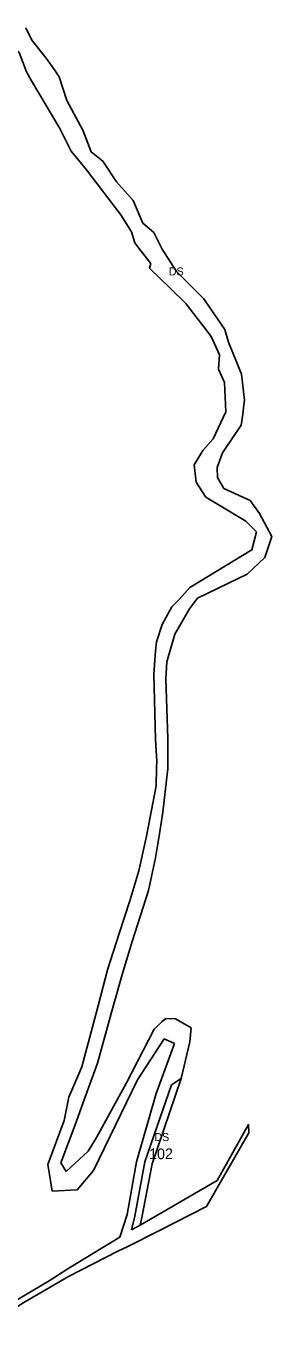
# Model space of a CAD drawing. Extents: x -477304 to -465641, y -1159113 to -1149285.
# Drawn here: x -468631 to -468355, y -1158263 to -1156790 of the extents above; entities that cross this region are included whole.
import ezdxf

# ---------------------------------------------------------------- set-up
doc = ezdxf.new("R2010")
doc.units = 0
for name, color, linetype in [('14', 7, 'Continuous'), ('35', 7, 'Continuous'), ('60', 7, 'Continuous')]:
    doc.layers.add(name, color=color, linetype=linetype)

msp = doc.modelspace()

# ---------------------------------------------------------------- linework, layer by layer
at = {"layer": '14'}
for p, q in [((-468456.8, -1157973.4), (-468467.9, -1157980.6)), ((-468467.9, -1157980.6), (-468497.7, -1158067.2)), ((-468497.7, -1158067.2), (-468509.1, -1158128.1)), ((-468509.1, -1158128.1), (-468512.6, -1158143.7)), ((-468512.6, -1158143.7), (-468503, -1158138.1)), ((-468503, -1158138.1), (-468501.1, -1158129.7))]:
    msp.add_line(p, q, dxfattribs=at)
msp.add_lwpolyline([(-468501.1, -1158129.7), (-468489.7, -1158069.3), (-468456.8, -1157973.4)], dxfattribs=at)
at = {"layer": '35'}
for p, q in [((-468630.9, -1156841.5), (-468625.1, -1156851.4)), ((-468594.2, -1156847.1), (-468599.5, -1156839.4)), ((-468625.1, -1156851.4), (-468593.4, -1156905.3)), ((-468558.2, -1156931.4), (-468567.6, -1156907)), ((-468563.5, -1156951.5), (-468551.2, -1156967.3)), ((-468551.2, -1156967.3), (-468539.3, -1156983.1)), ((-468510.8, -1156986.2), (-468529.8, -1156965.2)), ((-468500.2, -1157011.6), (-468510.8, -1156986.2)), ((-468512.9, -1157021.4), (-468509.2, -1157033.6)), ((-468509.2, -1157033.6), (-468504.6, -1157039.7)), ((-468478.4, -1157040.7), (-468480.9, -1157035.7)), ((-468504.6, -1157039.7), (-468491.1, -1157057.1)), ((-468468.9, -1157085.1), (-468451.6, -1157102.1)), ((-468431.5, -1157128.2), (-468423.1, -1157139.1)), ((-468387.7, -1157226.2), (-468386.3, -1157215.7)), ((-468408.8, -1157310.1), (-468416.2, -1157297.5)), ((-468440.2, -1157302.8), (-468429, -1157319.8)), ((-468379.4, -1157323.3), (-468408.8, -1157310.1)), ((-468429, -1157319.8), (-468384, -1157346.8)), ((-468384, -1157346.8), (-468372.1, -1157358.5)), ((-468382.6, -1157406.1), (-468362.7, -1157387.5)), ((-468459, -1157434.9), (-468467.3, -1157443.2)), ((-468473, -1157504.8), (-468463.9, -1157473.9)), ((-468485.8, -1157492.8), (-468487.6, -1157518.9)), ((-468474.1, -1157524.1), (-468473, -1157504.8)), ((-468484.5, -1157623.9), (-468485, -1157644.1)), ((-468493.8, -1157762.1), (-468485.9, -1157725.4)), ((-468512.2, -1157819.4), (-468493.8, -1157762.1)), ((-468549.7, -1157890.2), (-468568.8, -1157960.1)), ((-468506, -1157974.8), (-468475.9, -1157928.9)), ((-468475.9, -1157928.9), (-468464.3, -1157934.1)), ((-468456.8, -1157973.4), (-468447, -1157932.2)), ((-468555.4, -1158076.8), (-468506, -1157974.8)), ((-468518.3, -1157978.3), (-468552, -1158039.6)), ((-468467.9, -1157980.6), (-468456.8, -1157973.4)), ((-468497.7, -1158067.2), (-468467.9, -1157980.6)), ((-468588.5, -1158020.6), (-468606.8, -1158070.2)), ((-468592.2, -1158068), (-468576.1, -1158025.3)), ((-468552, -1158039.6), (-468561.6, -1158054.9)), ((-468561.6, -1158054.9), (-468586.1, -1158077.9)), ((-468507, -1158067.1), (-468517.8, -1158126.2)), ((-468606.8, -1158070.2), (-468605.3, -1158078.9)), ((-468605.3, -1158078.9), (-468601.9, -1158100.2)), ((-468586.1, -1158077.9), (-468592.2, -1158068)), ((-468573.7, -1158098.6), (-468555.4, -1158076.8)), ((-468416.5, -1158088.1), (-468503, -1158138.1)), ((-468601.9, -1158100.2), (-468573.7, -1158098.6)), ((-468517.8, -1158126.2), (-468526, -1158151.8)), ((-468503, -1158138.1), (-468512.6, -1158143.7)), ((-468528, -1158167.5), (-468527.2, -1158167.2)), ((-468605.2, -1158200.9), (-468696.7, -1158254.6))]:
    msp.add_line(p, q, dxfattribs=at)
for points in [[(-468674.6, -1156780.1), (-468664.6, -1156788.5), (-468654.5, -1156806.2), (-468639.1, -1156819.7), (-468630.9, -1156841.5)], [(-468599.5, -1156839.4), (-468608.7, -1156826.1), (-468625, -1156805.8), (-468631.6, -1156792)], [(-468567.6, -1156907), (-468585.5, -1156873.7), (-468594.2, -1156847.1)], [(-468593.4, -1156905.3), (-468580.6, -1156930.7), (-468563.5, -1156951.5)], [(-468529.8, -1156965.2), (-468544.9, -1156941.8), (-468558.2, -1156931.4)], [(-468539.3, -1156983.1), (-468524.8, -1157002.4), (-468512.9, -1157021.4)], [(-468480.9, -1157035.7), (-468487.5, -1157022.2), (-468500.2, -1157011.6)], [(-468403.6, -1157145.6), (-468407.7, -1157131.3), (-468424.2, -1157107.1), (-468431.3, -1157096.7), (-468462.1, -1157065.9), (-468478.4, -1157040.7)], [(-468491.1, -1157057.1), (-468492.4, -1157062.1), (-468468.9, -1157085.1)], [(-468451.6, -1157102.1), (-468449.4, -1157105), (-468431.5, -1157128.2)], [(-468423.1, -1157139.1), (-468413.9, -1157159.7), (-468415.1, -1157175.9)], [(-468386.3, -1157215.7), (-468385.7, -1157210.7), (-468388.9, -1157181.4), (-468403.6, -1157145.6)], [(-468415.1, -1157175.9), (-468408.3, -1157190.7), (-468406.5, -1157223.7), (-468421, -1157254.1), (-468432.5, -1157267.4), (-468442.3, -1157283.5), (-468440.2, -1157302.8)], [(-468416.2, -1157297.5), (-468416.6, -1157286.5), (-468410.3, -1157269.9), (-468389.3, -1157238.7), (-468387.7, -1157226.2)], [(-468363.5, -1157347.8), (-468368.8, -1157338.2), (-468379.4, -1157323.3)], [(-468372.1, -1157358.5), (-468377.3, -1157379), (-468447.3, -1157421.3), (-468459, -1157434.9)], [(-468362.7, -1157387.5), (-468355, -1157363.8), (-468363.5, -1157347.8)], [(-468463.9, -1157473.9), (-468447.6, -1157445.1), (-468438.7, -1157433.4), (-468382.6, -1157406.1)], [(-468467.3, -1157443.2), (-468478.2, -1157462.9), (-468484.8, -1157482.3), (-468485.8, -1157492.8)], [(-468487.6, -1157518.9), (-468485.6, -1157591.9), (-468484.6, -1157610.8)], [(-468471.8, -1157621.2), (-468472, -1157591), (-468474.1, -1157524.1)], [(-468484.6, -1157610.8), (-468484.4, -1157616.2), (-468484.5, -1157623.9)], [(-468485.9, -1157725.4), (-468481.4, -1157698.1), (-468477.7, -1157673.8), (-468471.8, -1157624.7), (-468471.8, -1157621.2)], [(-468485, -1157644.1), (-468496, -1157701), (-468504.5, -1157740), (-468514.5, -1157773.6), (-468526.8, -1157810.4)], [(-468526.8, -1157810.4), (-468539.7, -1157851.2), (-468549.7, -1157890.2)], [(-468551, -1157956.1), (-468533.7, -1157893.4), (-468522.2, -1157852.5), (-468512.2, -1157819.4)], [(-468478.2, -1157909.1), (-468487.4, -1157918), (-468518.3, -1157978.3)], [(-468463.3, -1157906.4), (-468474.1, -1157906), (-468478.2, -1157909.1)], [(-468447, -1157932.2), (-468445.8, -1157916.4), (-468463.3, -1157906.4)], [(-468464.3, -1157934.1), (-468485.1, -1157990.4), (-468507, -1158067.1)], [(-468568.8, -1157960.1), (-468583.1, -1157994.5), (-468588.5, -1158020.6)], [(-468576.1, -1158025.3), (-468567, -1158000.5), (-468551, -1157956.1)], [(-468516.8, -1158162.2), (-468482, -1158144.5), (-468428.3, -1158117.4), (-468380.7, -1158034.3), (-468381.3, -1158025.2), (-468416.5, -1158088.1)], [(-468512.6, -1158143.7), (-468509.1, -1158128.1), (-468497.7, -1158067.2)], [(-468526, -1158151.8), (-468583.2, -1158186.8), (-468605.2, -1158200.9)], [(-468694.3, -1158262.7), (-468685.3, -1158257.8), (-468633.7, -1158225.4), (-468583.8, -1158195.8), (-468528, -1158167.5)], [(-468527.2, -1158167.2), (-468518.4, -1158163), (-468516.8, -1158162.2)]]:
    msp.add_lwpolyline(points, dxfattribs=at)

# ---------------------------------------------------------------- texts
at = {"layer": '14'}
msp.add_text('DS', height=9, dxfattribs=at).set_placement((-468487, -1158043.7))
at = {"layer": '35'}
msp.add_text('DS', height=9, dxfattribs=at).set_placement((-468470.8, -1157070.4))
at = {"layer": '60'}
msp.add_text('102', height=12, dxfattribs=at).set_placement((-468493, -1158064))

doc.saveas('drawing.dxf')
